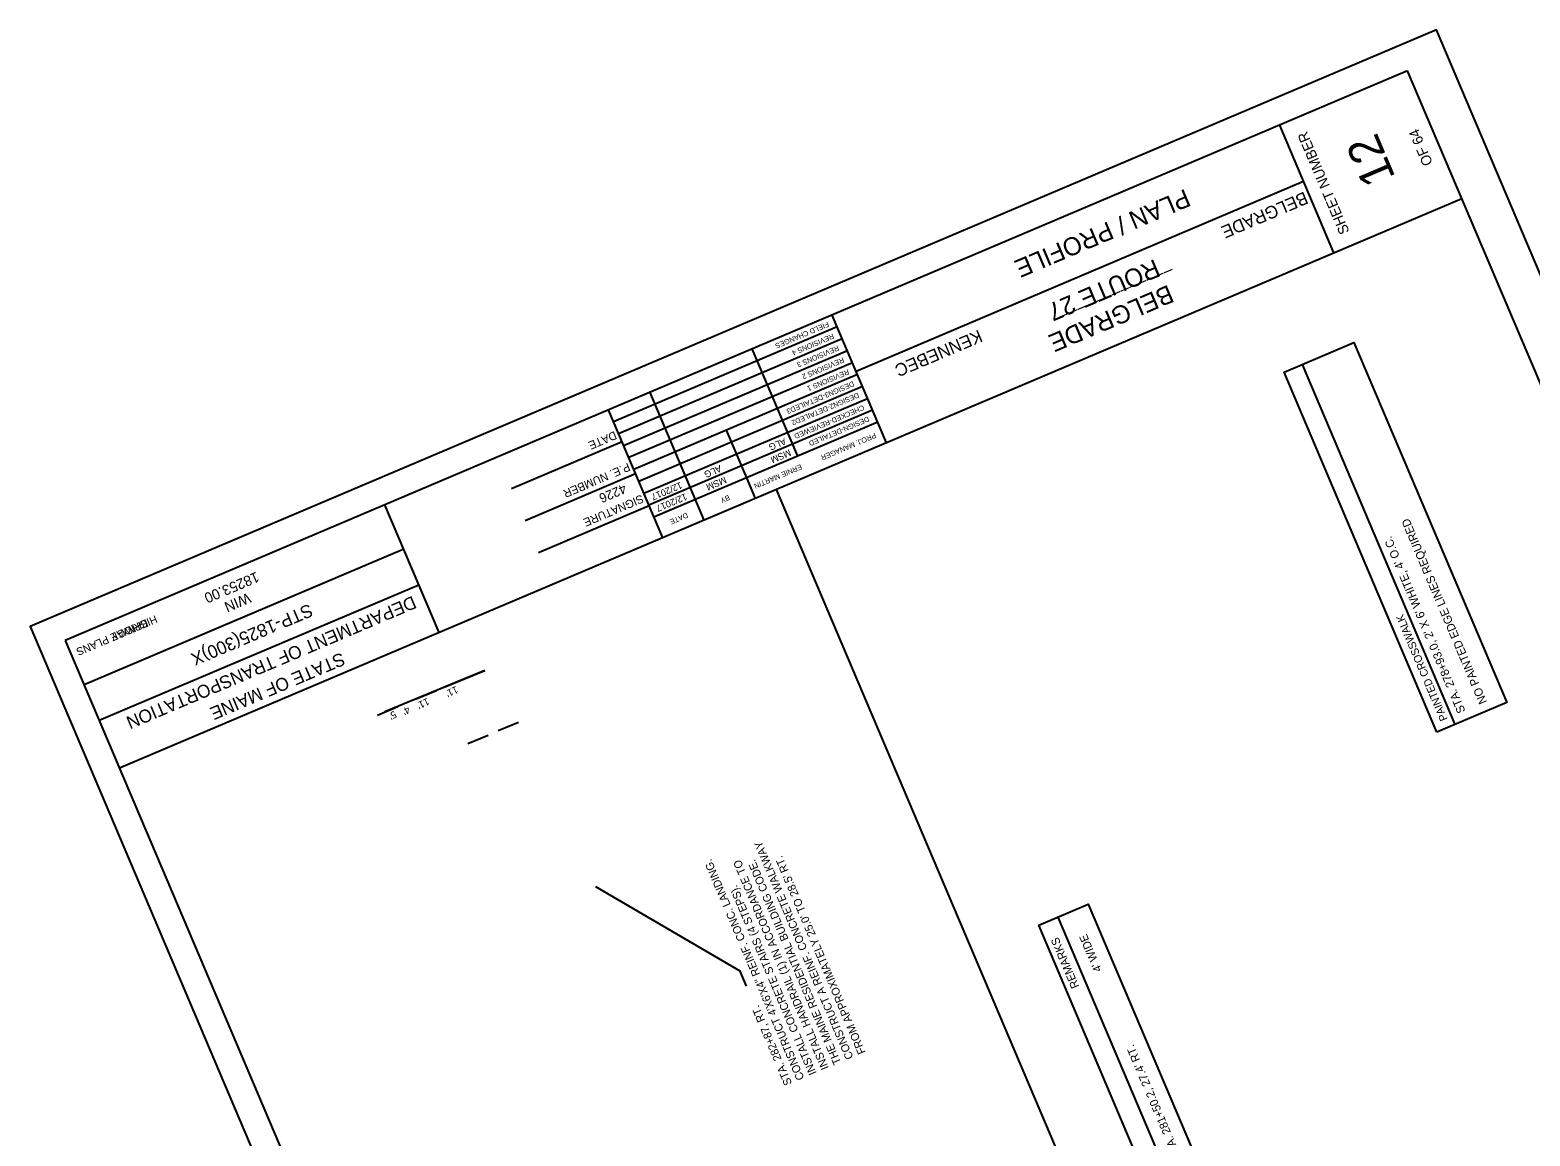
# Model space of a CAD drawing. Extents: x 1111260 to 1112098, y 617053 to 618050.
# Drawn here: x 1111260 to 1111800, y 617652 to 618050 of the extents above; entities that cross this region are included whole.
import ezdxf

# ---------------------------------------------------------------- set-up
doc = ezdxf.new("R2010")
doc.units = 0
for name, color, linetype in [('H_V ANNOTATION', 7, 'Continuous'), ('MINOR', 7, 'Continuous'), ('S_Roadway_Centerline', 7, 'Continuous'), ('S_Roadway_Sidewalks_Paved', 7, 'Continuous'), ('S_Utilities_GuyWire3', 7, 'Continuous')]:
    doc.layers.add(name, color=color, linetype=linetype)

msp = doc.modelspace()

# ---------------------------------------------------------------- linework, layer by layer
at = {"layer": 'MINOR'}
for p, q in [((1111755.5, 618035.73), (1111272.23, 617830.6)), ((1112068.1, 617299.33), (1111755.51, 618035.74)), ((1111729.01, 617970.17), (1111709.47, 618016.19)), ((1111718.09, 617995.9), (1111557, 617927.52)), ((1111775.03, 617989.7), (1111291.77, 617784.57)), ((1111567.92, 617901.79), (1111548.38, 617947.82)), ((1111487.38, 617867.6), (1111467.84, 617913.63)), ((1111472.72, 617902.12), (1111432.92, 617885.23)), ((1111477.61, 617890.61), (1111437.81, 617873.72)), ((1111821.4, 617194.62), (1111528.35, 617884.99)), ((1111406.87, 617833.43), (1111387.34, 617879.45)), ((1111482.49, 617879.11), (1111442.69, 617862.21)), ((1111394.12, 617863.45), (1111279.05, 617814.61)), ((1111399.58, 617850.58), (1111284.51, 617801.74)), ((1111272.25, 617830.6), (1111584.83, 617094.2))]:
    msp.add_line(p, q, dxfattribs=at)
for points in [[(1111550.19, 617943.53), (1111469.66, 617909.34)], [(1111552.01, 617939.24), (1111471.48, 617905.05)], [(1111553.83, 617934.95), (1111473.3, 617900.77)], [(1111536, 617897.01), (1111519.62, 617935.6)], [(1111555.65, 617930.66), (1111475.12, 617896.48)], [(1111557.47, 617926.37), (1111476.94, 617892.19)], [(1111559.29, 617922.09), (1111478.76, 617887.9)], [(1111480.58, 617883.61), (1111561.11, 617917.8)], [(1111502.34, 617873.95), (1111482.8, 617919.98)], [(1111562.93, 617913.51), (1111482.4, 617879.33)], [(1111564.75, 617909.22), (1111487.47, 617876.42)], [(1111517.59, 617889.2), (1111510.31, 617906.35)], [(1111520.75, 617881.77), (1111517.59, 617889.2)], [(1111499.18, 617881.38), (1111484.22, 617875.03)]]:
    msp.add_lwpolyline(points, dxfattribs=at)
at = {"layer": 'S_Roadway_Sidewalks_Paved'}
msp.add_lwpolyline([(1112097.99, 617268.06), (1111765.87, 618050.49), (1111259.59, 617835.59), (1111591.71, 617053.16)], close=True, dxfattribs=at)
at = {"layer": 'S_Utilities_GuyWire3'}
for p, q in [((1111772.68, 617800.4), (1111717.66, 617930.03)), ((1111423.31, 617819.84), (1111416, 617816.8)), ((1111416, 617816.8), (1111423.31, 617819.84)), ((1111413.19, 617815.63), (1111405.88, 617812.58)), ((1111408.69, 617813.76), (1111416, 617816.8)), ((1111403, 617811.39), (1111395.7, 617808.34)), ((1111398.57, 617809.54), (1111405.88, 617812.58)), ((1111384.69, 617803.76), (1111392, 617806.81)), ((1111435.48, 617801.12), (1111428.17, 617798.08)), ((1111433.38, 617800.28), (1111428.17, 617798.08)), ((1111417.17, 617793.49), (1111424.48, 617796.53)), ((1111689.19, 617590.79), (1111629.68, 617730.98))]:
    msp.add_line(p, q, dxfattribs=at)
for points in [[(1111766.06, 617797.58), (1111711.04, 617927.22), (1111736.16, 617937.88), (1111791.19, 617808.25)], [(1111682.21, 617587.83), (1111622.71, 617728.02), (1111640.55, 617735.59), (1111700.05, 617595.4)]]:
    msp.add_lwpolyline(points, close=True, dxfattribs=at)
for points in [[(1111416, 617816.8), (1111387.38, 617804.88)], [(1111517.51, 617706.05), (1111515.19, 617711.52), (1111463.34, 617741.87)]]:
    msp.add_lwpolyline(points, dxfattribs=at)

# ---------------------------------------------------------------- texts
at = {"layer": 'H_V ANNOTATION'}
for s, height, p in [('BELGRADE', 4.536, (1111718.38, 617992.38)), ('_____________', 4.5358, (1111671.18, 617963.24)), ('KENNEBEC', 4.536, (1111601.18, 617942.63)), ('BRIDGE PLANS', 2.795, (1111301.4, 617838.4))]:
    msp.add_text(s, height=height, rotation=203, dxfattribs=at).set_placement(p)
at = {"layer": 'MINOR'}
for s, height, rotation, p in [('SHEET NUMBER', 3.7264, 113, (1111734.66, 617977.81)), ('12', 12.097, 113, (1111751.25, 617997.38)), ('OF 64', 3.726, 113, (1111764.66, 618002.5)), ('PLAN / PROFILE', 6.5214, 203, (1111675.46, 617993.42)), ('FIELD CHANGES', 1.8637, 203, (1111546.72, 617945.49)), ('REVISIONS 4', 1.8637, 203, (1111548.54, 617941.21)), ('REVISIONS 3', 1.8637, 203, (1111550.36, 617936.92)), ('REVISIONS 2', 1.8637, 203, (1111552.18, 617932.63)), ('REVISIONS 1', 1.8637, 203, (1111554, 617928.34)), ('DESIGN3-DETAILED3', 1.8637, 203, (1111555.82, 617924.05)), ('DESIGN2-DETAILED2', 1.8637, 203, (1111557.57, 617919.94)), ('CHECKED-REVIEWED', 1.8637, 203, (1111559.46, 617915.48)), ('DESIGN-DETAILED', 1.8637, 203, (1111561.21, 617911.36)), ('DATE', 2.953, 203, (1111470, 617906.08)), ('PROJ. MANAGER', 1.8637, 203, (1111563.71, 617905.46)), ('ALG', 2.423, 203, (1111531.15, 617903.66)), ('MSM', 2.423, 203, (1111532.9, 617899.54)), ('P.E. NUMBER', 2.9528, 203, (1111474.85, 617894.66)), ('ERNIE MARTIN', 1.8637, 203, (1111537, 617894.12)), ('ALG', 2.423, 203, (1111507.94, 617893.81)), ('MSM', 2.423, 203, (1111509.69, 617889.69)), ('12/2017', 2.423, 203, (1111493.75, 617887.78)), ('12/2017', 2.423, 203, (1111495.5, 617883.67)), ('SIGNATURE', 2.953, 203, (1111479.69, 617883.24)), ('BY', 1.857, 203, (1111511.03, 617883.1)), ('DATE', 1.857, 203, (1111495.97, 617876.71)), ('18253.00', 3.726, 203, (1111341.08, 617855.45)), ('DEPARTMENT OF TRANSPORTATION', 4.6588, 203, (1111397.33, 617846.8)), ('WIN', 3.726, 203, (1111338.08, 617847.88)), ('STP-1825(300)X', 4.6588, 203, (1111360.15, 617843.97)), ('STATE OF MAINE', 4.6588, 203, (1111371.73, 617826.42))]:
    msp.add_text(s, height=height, rotation=rotation, dxfattribs=at).set_placement(p)
at = {"layer": 'S_Roadway_Centerline'}
for s, height, p in [('ROUTE 27', 6.521, (1111664.54, 617968.11)), ('BELGRADE', 6.521, (1111669.42, 617958.85)), ('HIGHWAY PLANS', 2.795, (1111304.66, 617839.79))]:
    msp.add_text(s, height=height, rotation=203, dxfattribs=at).set_placement(p)
at = {"layer": 'S_Utilities_GuyWire3'}
for s, height, rotation, p in [('4226', 3.396, 203, (1111473.4, 617887.09)), ('NO PAINTED EDGE LINES REQUIRED', 3.0059, 112.9989, (1111784.16, 617808.45)), ("STA. 278+93.0, 2' X 6' WHITE, 4' O.C.", 3.0059, 112.9989, (1111776.39, 617805.15)), ('PAINTED CROSSWALK', 2.8055, 112.9989, (1111769.97, 617802.29)), ("11'", 2.55, 205.7961, (1111412.94, 617814.29)), ("11'", 2.55, 205.7961, (1111402.6, 617809.99)), ("5'", 2.55, 207.0946, (1111390.72, 617805.39)), ("4'", 2.55, 207.0946, (1111395.61, 617807.03)), ('CONSTRUCT A REINF. CONCRETE WALKWAY', 2.88, 113, (1111556.07, 617680.43)), ('CONSTRUCT 4\'X6\'X4" REINF. CONC. LANDING.', 2.88, 113, (1111538.39, 617672.92)), ('INSTALL HANDRAIL (1) IN ACCORDANCE TO', 2.88, 113, (1111547.23, 617676.68)), ('THE MAINE RESIDENTIAL BUILDING CODE.', 2.88, 113, (1111551.65, 617678.55)), ("FROM APPROXIMATELY 25.0' TO 28.5' RT.", 2.88, 113, (1111560.48, 617682.3)), ('INSTALL CONCRETE STAIRS (4 STEPS).', 2.88, 113, (1111542.81, 617674.8)), ('REMARKS', 2.953, 113, (1111637.35, 617706)), ("4' WIDE", 2.953, 113, (1111645.51, 617711.96)), ('STA. 282+87, RT.', 2.88, 113, (1111533.97, 617671.05)), ("STA. 281+25.9, 15.0' RT. TO STA. 281+50.2, 27.4' RT.", 2.9531, 113, (1111694.61, 617596.29))]:
    msp.add_text(s, height=height, rotation=rotation, dxfattribs=at).set_placement(p)

doc.saveas('drawing.dxf')
